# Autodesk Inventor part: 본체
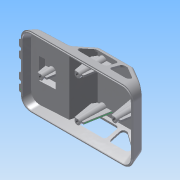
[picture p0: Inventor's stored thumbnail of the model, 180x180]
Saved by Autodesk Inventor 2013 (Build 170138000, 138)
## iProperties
Created: 2015-05
Part Number: 본체
Material: ABS 플라스틱
Document SubType Name: Modeling
Designer: Administrator
Density: 7.85 g/cm^3
Mass: 239.611 g
Surface Area: 315.025 cm^2
Volume: 30.5238 cm^3
Author: Administrator
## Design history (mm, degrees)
sketch "스케치1"
  geometry: L1 (0, 0)-(122, 0); L2 (92, 30)-(53.826, 30); L3 (53.826, 30)-(42, 11.075); L4 (42, 11.075)-(2.412, 9); L5 (2.412, 9)-(0, 0); L6 (122, 0)-(122, 10); L7 (92, 30)-(122, 10); L8 (122, 0)-(118.738, 12.175)
  constraints: 16 end point, 1 horizontal, 1 parallel, 1 perpendicular, 1 point on line
  dimensions: "d0" = 122 distance of L1.start L1.end; "d1" = 105 deg angle of L1 L5; "d2" = 30 distance between parallel lines of L2 L1; "d3" = 30 horizontal distance of L1.end L2.start; "d4" = 9 vertical distance of L1.start L4.end; "d6" = 3 deg angle of L1 L4; "d9" = 125 deg angle of L3 L4; "d10" = 42 horizontal distance of L1.start L3.end; "d33" = 20 vertical distance of L6.end L2.start; "d34" = 105 deg angle of L1 L8
node "작업 평면1"
extrude "돌출4" new body sketch "스케치1" stored distance "d35" = 76; taper "d36" = 0 deg
node "작업 평면4"
sketch "스케치7"
  geometry: L1 (12.175, 38)-(30, 38) reference; L2 (0, 38)-(12.175, 38) reference; L3 (0, -38)-(0, 38) reference; L4 (30, -38)-(30, 38) reference; L5 (30, -38)-(12.175, -38) reference; L6 (12.175, -38)-(0, -38) reference; L7 (0, -38)-(30, -29.962); L8 (0, 38)-(30, 29.962); 1 further point
  constraints: 4 end point, 2 point on line
  dimensions: "d40" = 105 deg angle of L3 L7; "d41" = 105 deg angle of L3 L8
extrude "돌출5" cut sketch "스케치7" stored distance "d42" = 76; taper "d43" = 0 deg
sketch "스케치9"
  geometry: L1 (8.121, 48.588)-(28.121, 48.588); L2 (28.121, 48.588)-(28.121, 22.588); L3 (28.121, 22.588)-(8.121, 22.588); L4 (8.121, 22.588)-(8.121, 48.588); L5 (8.121, 48.588)-(28.121, 22.588); L6 (28.121, 48.588)-(8.121, 22.588); L7 (-2.879, -2.412)-(-2.879, 73.588) reference; 4 further points
  constraints: 12 end point, 4 midpoint, 2 parallel, 1 horizontal, 1 horizontal alignment, 1 perpendicular
  dimensions: "d53" = 11 distance between parallel lines of L4 L7; "d54" = 20 distance between parallel lines of L2 L4; "d55" = 26 distance between parallel lines of L3 L1
extrude "돌출7" join sketch "스케치9" distance "d56" = 5; taper "d57" = -20 deg
fillet "모깎기1" dims "d69" = 12
feature "쉘2" dims "d44" = 2
node "작업 평면5"
sketch "스케치8"
  geometry: L1 (42, 11.075)-(53.826, 30) reference; L2 (53.826, 30)-(92, 30) reference; L3 (112.986, 10)-(90.486, 25); L4 (90.486, 25)-(56.597, 25); L5 (56.597, 25)-(47.224, 10); L6 (47.224, 10)-(112.986, 10); L7 (81.224, 25)-(81.224, 10); L8 (84.986, 25)-(84.986, 10); 3 further points; 1 other entity
  constraints: 12 end point, 4 point on line, 2 perpendicular, 1 parallel, 2 other
  dimensions: "d46" = 5 distance between parallel lines of L4 L2; "d47" = 15 distance between parallel lines of L6 L4; "d48" = 5 dimension on L3; "d49" = 34 distance of L7.end L5.end; "d50" = 28 distance of L3.start L8.end
extrude "돌출6" cut sketch "스케치8" stored distance "d51" = 76; taper "d52" = 0 deg
node "작업 평면6"
sketch "스케치14"
  geometry: L1 (98.679, -73.929)-(0.139, -73.929) reference; L2 (-9.521, -64.27)-(-9.521, -11.73) reference; L3 (0.139, -2.071)-(98.679, -2.071) reference; L4 (108.338, -11.73)-(108.338, -64.27) reference; L5 (98.679, -1.071)-(0.139, -1.071); L6 (-10.521, -11.73)-(-10.521, -64.27); L7 (0.139, -74.929)-(98.679, -74.929); L8 (109.338, -64.27)-(109.338, -11.73); 5 further points; 4 other entities
  constraints: 8 end point, 7 parallel, 16 other
  dimensions: "d87" = 1 distance between parallel lines of L3 L5
extrude "돌출10" join sketch "스케치14" distance "d88" = 1; taper "d89" = 0 deg
node "작업 평면9"
sketch "스케치15" dims "d103" = 4
  geometry: L1 (0, 25)-(0, -25); C1 r 4 at (0, -10); C2 r 4 at (0, 10); 6 further points
  constraints: 2 centre point, 2 end point, 2 vertical alignment, 1 equal radius, 13 other
  dimensions: "d105" = 20 distance of C1.centre C2.centre; "d106" = 10 distance of C1.centre point (0, 0); "d107" = 11 distance of C1.centre point (0, -21); "d108" = 11 distance of C2.centre point (0, 21)
extrude "돌출11" join sketch "스케치15" stored distance "d109" = 1; taper "d110" = 0 deg
sketch "스케치16"
  geometry: L1 (-35, 0)-(-27, 0); L2 (-24, 0)-(-16, 0); L3 (-4, 0)-(4, 0); L4 (7, 0)-(15, 0); A1 r 4 centre (0, 0) between (-4, 0) and (4, 0) reference; A2 r 4 centre (-31, 0) between (-35, 0) and (-27, 0) reference; A3 r 4 centre (-20, 0) between (-24, 0) and (-16, 0) reference; A4 r 4 centre (11, 0) between (7, 0) and (15, 0) reference; 1 further point
  constraints: 8 end point, 8 point on circle, 3 collinear, 2 point on line, 1 horizontal
  dimensions: "d111" = 8 distance of L1.start L1.end; "d112" = 8 distance of L2.start L2.end
extrude "돌출12" cut sketch "스케치16" stored distance "d113" = 1; taper "d114" = 0 deg
sketch "스케치17"
  geometry: 1 further point
node "작업 평면10"
sketch "스케치18"
  geometry: L1 (110.409, 11.591)-(110.409, 64.409) reference; L2 (-11.591, 44)-(-11.591, 32) reference; C1 r 3 at (9.409, 38); C2 r 3 at (89.409, 38); C3 r 3 at (49.409, 60); C4 r 3 at (49.409, 16); 2 further points
  constraints: 4 centre point, 3 equal radius, 2 horizontal alignment, 1 midpoint, 1 vertical alignment
  dimensions: "d116" = 6 diameter of C1; "d118" = 21 distance from line of C2.centre L1; "d119" = 40 horizontal distance of C4.centre C2.centre; "d120" = 40 horizontal distance of C4.centre C1.centre; "d121" = 44 distance of C4.centre C3.centre; "d122" = 22 vertical distance of C2.centre C4.centre
extrude "돌출13" join sketch "스케치18" stored distance "d123" = 1; taper "d124" = 2 deg
node "작업 평면11"
node "작업 평면12"
sketch "스케치21"
  geometry: L1 (-5, 1)-(5, 1); L2 (5, 1)-(5, -1); L3 (5, -1)-(-5, -1); L4 (-5, -1)-(-5, 1); L5 (-5, 1)-(5, -1); L6 (5, 1)-(-5, -1); L7 (-5, -43)-(5, -43); L8 (5, -43)-(5, -45); L9 (5, -45)-(-5, -45); L10 (-5, -45)-(-5, -43); L11 (-5, -43)-(5, -45); L12 (5, -43)-(-5, -45); L13 (35, -21)-(45, -21); L14 (45, -21)-(45, -23); L15 (45, -23)-(35, -23); L16 (35, -23)-(35, -21); L17 (35, -21)-(45, -23); L18 (45, -21)-(35, -23); L19 (-45, -21)-(-35, -21); L20 (-35, -21)-(-35, -23); L21 (-35, -23)-(-45, -23); L22 (-45, -23)-(-45, -21); L23 (-45, -21)-(-35, -23); L24 (-35, -21)-(-45, -23); C1 r 3 at (0, 0) reference; C2 r 3 at (-40, -22) reference; C3 r 3 at (40, -22) reference; C4 r 3 at (0, -44) reference; 1 further point
  constraints: 48 end point, 8 midpoint, 8 parallel, 4 horizontal, 4 perpendicular
  dimensions: "d137" = 2 distance of L1.end L2.end; "d139" = 10 distance of L2.end L3.end; "d140" = 2 distance of L19.end L20.end; "d141" = 10 horizontal distance of L19.start L20.end; "d142" = 2 distance of L7.end L8.end; "d143" = 10 distance of L8.end L9.end; "d144" = 2 distance of L13.end L14.end; "d145" = 10 distance of L14.end L15.end
extrude "돌출15" join sketch "스케치21" stored distance "d146" = 2; taper "d147" = 0 deg
node "작업 평면13"
sketch "스케치23"
  geometry: L1 (16, 2)-(18.098, 2) reference; L2 (23.902, 2)-(26, 2) reference; L3 (96, 2)-(98.098, 2) reference; L4 (103.902, 2)-(106, 2) reference; L5 (16, 2)-(13.916, 13.82); L6 (26, 2)-(28.084, 13.82); L7 (13.916, 13.82)-(28.084, 13.82); L8 (96, 2)-(91.265, 28.856); L9 (91.265, 28.856)-(110.735, 28.856); L10 (110.735, 28.856)-(106, 2); L11 (16, 2)-(26, 2); L12 (96, 2)-(106, 2); 1 further point
  constraints: 16 end point, 3 parallel, 2 equal length, 1 collinear
  dimensions: "d149" = 20 deg angle of L6 L5; "d150" = 14.16846 distance of L5.end L6.end; "d152" = 20 deg angle of L8 L10; "d154" = 19.47074 distance of L8.end L9.end
extrude "돌출16" join sketch "스케치23" stored distance "d155" = 2; taper "d156" = 0 deg
sketch "스케치24"
  geometry: L1 (110.735, 28.856)-(93.717, 28.856) reference; L2 (108.945, 18.703)-(110.735, 28.856) reference; L3 (92, 30)-(104.626, 21.583) reference; L4 (104.626, 21.583)-(118.738, 12.175) reference; L5 (93.717, 28.856)-(110.735, 28.856); L6 (108.945, 18.703)-(110.735, 28.856); L7 (108.945, 18.703)-(93.717, 28.856); 1 further point
  constraints: 6 end point, 3 collinear
extrude "돌출17" cut sketch "스케치24" stored distance "d157" = 2; taper "d158" = 0 deg
fillet "모깎기2" dims "d166" = 3
fillet "모깎기3" dims "d167" = 3
fillet "모깎기4" dims "d168" = 3
chamfer "모따기1" distance "d169" = 1; stored, may be unused: second distance "d170" = 2, angle "d171" = 45 deg
node "작업 평면14"
sketch "스케치26"
  geometry: L1 (-7.902, 0)-(-5.805, 0) reference; L2 (-7.902, 0)-(-7.902, 26) reference; L3 (2.098, 0)-(2.098, 26) reference; L4 (0, 0)-(2.098, 0) reference; L5 (2.098, 0)-(6.875, 27.093); L6 (6.875, 27.093)-(-12.68, 27.093); L7 (-12.68, 27.093)-(-7.902, 0); L8 (-7.902, 0)-(2.098, 0); 1 further point
  constraints: 8 end point, 1 collinear, 1 equal length, 1 parallel
  dimensions: "d172" = 20 deg angle of L5 L7; "d173" = 19.55442 distance of L5.end L6.end
extrude "돌출18" join sketch "스케치26" stored distance "d176" = 2; taper "d177" = 0 deg
sketch "스케치27"
  geometry: L1 (-10.958, 26.59)-(-12.231, 24.551) reference; L2 (-10.563, 27.093)-(-12.68, 27.093) reference; L3 (-12.68, 27.093)-(-12.231, 24.551) reference; L4 (-10.958, 26.59)-(-12.231, 24.551) reference; L5 (-10.563, 27.093)-(-12.68, 27.093) reference; L6 (-12.68, 27.093)-(-12.231, 24.551) reference; A1 r 3 centre (-8.414, 25) between (-10.563, 27.093) and (-10.958, 26.59) reference; A2 r 3 centre (-8.414, 25) between (-10.563, 27.093) and (-10.958, 26.59) reference; 1 further point
extrude "돌출19" cut sketch "스케치27" stored distance "d178" = 2; taper "d179" = 0 deg
node "작업 평면15"
sketch "스케치28"
  geometry: L1 (-12.487, 26)-(-7.902, 0) reference; 1 further point
sketch "스케치29"
  geometry: L1 (-55.489, -33.66)-(-55.489, -21.66) reference; L2 (66.511, -1.251)-(66.511, -54.068) reference; 3 further points
  constraints: 1 horizontal alignment, 1 midpoint, 1 other
  dimensions: "d180" = 50 distance from line of L2 point (16.511, -27.66)
feature "엠보싱1" sketch "스케치29" dims "d0" = 122, "d1" = 105 deg, "d2" = 30, "d3" = 30, "d4" = 9, "d6" = 3 deg, "d9" = 125 deg, "d10" = 42, "d33" = 20, "d34" = 105 deg, "d181" = 0.5, "d182" = 0
sketch "스케치25"
  geometry: C1 r 3 at (0, 0) reference; C2 r 3 at (-40, -22) reference; C3 r 3 at (0, -44) reference; C4 r 3 at (40, -22) reference; 5 further points
  constraints: 4 coincident
hole "구멍1" sketch "스케치25" at (0, -44), (0, 0), (40, -22), (-40, -22) diameter "d159" = 3.242; stored, may be unused: countersink angle "d163" = 90 deg, drill point angle "d165" = 118 deg; dims "d160" = 9, "d161" = 4, "d162" = 2, "d164" = 11
node "솔리드2"
mirror "대칭1"
node "투영된 루프3"
node "투영된 루프4"
node "투영된 루프5"
other parameters: "d15" = 0, "d37" = 0, "d45" = 0, "d70" = -1, "d90" = -2, "d115" = 0, "d125" = 0, "d136" = -2, "d148" = 0
